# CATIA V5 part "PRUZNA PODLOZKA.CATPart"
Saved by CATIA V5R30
Part number: PRUZNA PODLOZKA
Bounding box of the stored display mesh (mm): x -2.5 to 0, y -8.048 to 8.048, z -7.952 to 8.05
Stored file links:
  C:\Users\ondra\Desktop\PŘÍLOHA P III\CATIA\PRUZNA PODLOZKA.CATPart
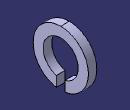
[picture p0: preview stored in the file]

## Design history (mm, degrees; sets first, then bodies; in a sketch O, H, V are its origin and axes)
Set1
  DatumSurface1 to DatumSurface8 "Z691/10x"
  Plane1: type Tangent, Support DatumSurface8, RefPoint vertex [face of DatumSurface8]
  Join1: Elements (DatumSurface1; DatumSurface2; DatumSurface3; DatumSurface4; DatumSurface5; DatumSurface6; DatumSurface7; DatumSurface8)
Body1 (main body)
  CloseSurface1: CloseElement Join1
